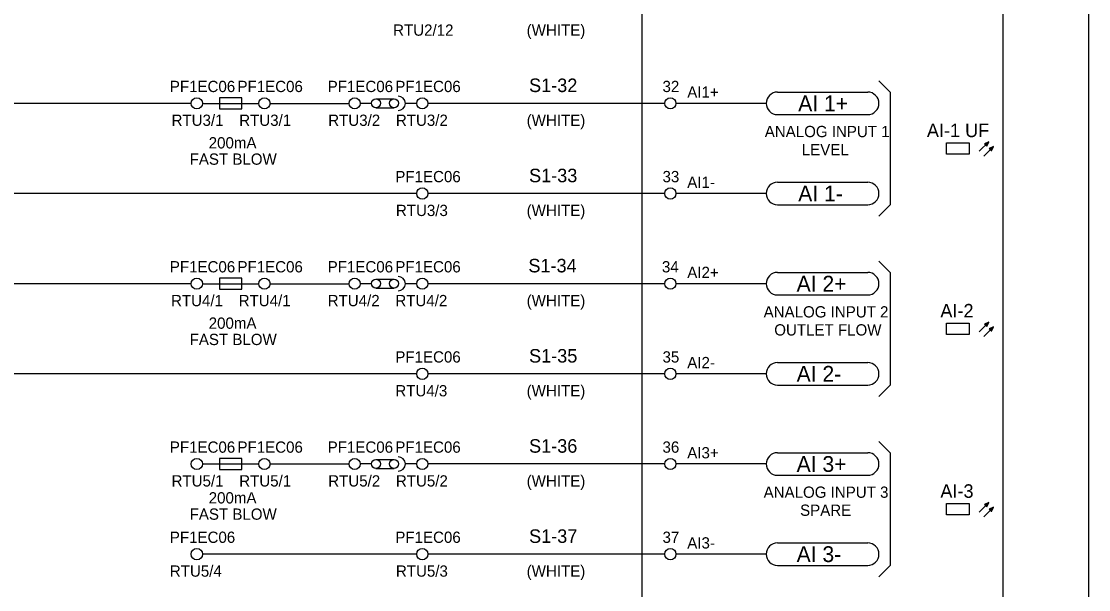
# Model space of a CAD drawing. Extents: x 0 to 841, y 0 to 594.
# Drawn here: x 592.3 to 829, y 132.1 to 258.2 of the extents above; entities that cross this region are included whole.
import ezdxf

# ---------------------------------------------------------------- set-up
doc = ezdxf.new("R2010")
doc.units = 0
for name, color, linetype in [('A1BORDER', 7, 'Continuous'), ('Level 1', 7, 'Continuous'), ('Level 10', 7, 'Continuous')]:
    doc.layers.add(name, color=color, linetype=linetype)

msp = doc.modelspace()

# ---------------------------------------------------------------- linework, layer by layer
at = {"layer": 'A1BORDER'}
msp.add_line((829, 581), (829, 15), dxfattribs=at)
at = {"layer": 'Level 1'}
for p, q in [((760, 242.5), (780, 242.5)), ((630, 240), (480, 240)), ((632.5, 240), (645, 240)), ((647.5, 240), (665, 240)), ((670, 240), (667.5, 240)), ((670.98, 241.03), (674.98, 241.03)), ((670.98, 239.03), (674.98, 239.03)), ((680, 240), (677.5, 240)), ((735, 240), (682.5, 240)), ((757.5, 240), (737.5, 240)), ((760, 237.5), (780, 237.5)), ((760, 222.5), (780, 222.5)), ((680, 220), (480, 220)), ((735, 220), (682.5, 220)), ((757.5, 220), (737.5, 220)), ((760, 217.5), (780, 217.5)), ((760, 202.5), (780, 202.5)), ((630, 200), (480, 200)), ((632.5, 200), (645, 200)), ((647.5, 200), (665, 200)), ((670, 200), (667.5, 200)), ((670.98, 201.03), (674.98, 201.03)), ((670.98, 199.03), (674.98, 199.03)), ((680, 200), (677.5, 200)), ((735, 200), (682.5, 200)), ((757.5, 200), (737.5, 200)), ((760, 197.5), (780, 197.5)), ((760, 182.5), (780, 182.5)), ((680, 180), (480, 180)), ((735, 180), (682.5, 180)), ((757.5, 180), (737.5, 180)), ((760, 177.5), (780, 177.5)), ((670.98, 161.03), (674.98, 161.03)), ((760, 162.5), (780, 162.5)), ((632.5, 160), (645, 160)), ((647.5, 160), (665, 160)), ((670, 160), (667.5, 160)), ((670.98, 159.03), (674.98, 159.03)), ((680, 160), (677.5, 160)), ((735, 160), (682.5, 160)), ((757.5, 160), (737.5, 160)), ((760, 157.5), (780, 157.5)), ((760, 142.5), (780, 142.5)), ((680, 140), (632.5, 140)), ((735, 140), (682.5, 140)), ((757.5, 140), (737.5, 140)), ((760, 137.5), (780, 137.5))]:
    msp.add_line(p, q, dxfattribs=at)
for points in [[(810, 553.95), (810, 80), (730, 80), (730, 546.05)], [(782.5, 245), (785, 242.5), (785, 217.5), (782.5, 215)], [(782.5, 205), (785, 202.5), (785, 177.5), (782.5, 175)], [(782.5, 165), (785, 162.5), (785, 137.5), (782.5, 135)]]:
    msp.add_lwpolyline(points, dxfattribs=at)
for points in [[(636.25, 238.75), (641.25, 238.75), (641.25, 241.25), (636.25, 241.25)], [(797.5, 231.25), (802.5, 231.25), (802.5, 228.75), (797.5, 228.75)], [(636.25, 198.75), (641.25, 198.75), (641.25, 201.25), (636.25, 201.25)], [(797.5, 191.25), (802.5, 191.25), (802.5, 188.75), (797.5, 188.75)], [(636.25, 158.75), (641.25, 158.75), (641.25, 161.25), (636.25, 161.25)], [(797.5, 151.25), (802.5, 151.25), (802.5, 148.75), (797.5, 148.75)]]:
    msp.add_lwpolyline(points, close=True, dxfattribs=at)
for centre in [(670.98, 240.03), (674.98, 240.03), (670.98, 200.03), (674.98, 200.03), (670.98, 160.03), (674.98, 160.03)]:
    msp.add_circle(centre, 1, dxfattribs=at)
for centre, start, end in [((760, 240), 90, 270), ((780, 240), 270, 90), ((760, 220), 90, 270), ((780, 220), 270, 90), ((760, 200), 90, 270), ((780, 200), 270, 90), ((760, 180), 90, 270), ((780, 180), 270, 90), ((760, 160), 90, 270), ((780, 160), 270, 90), ((760, 140), 90, 270), ((780, 140), 270, 90)]:
    msp.add_arc(centre, 2.5, start, end, dxfattribs=at)
at = {"layer": 'Level 10'}
for p, q in [((804.73, 229.36), (806.86, 231.48)), ((805.79, 228.3), (807.91, 230.42)), ((805.96, 231.08), (806.67, 231.08)), ((806, 230.93), (806.61, 230.93)), ((806.14, 230.78), (806.53, 230.78)), ((806.29, 231.22), (806.74, 231.22)), ((806.3, 230.62), (806.47, 230.62)), ((806.62, 231.38), (806.81, 231.38)), ((807.02, 230.02), (807.73, 230.02)), ((807.06, 229.87), (807.66, 229.87)), ((807.21, 229.72), (807.6, 229.72)), ((807.35, 230.16), (807.8, 230.16)), ((807.36, 229.56), (807.53, 229.56)), ((807.68, 230.31), (807.87, 230.31)), ((804.73, 189.35), (806.86, 191.48)), ((805.79, 188.3), (807.91, 190.42)), ((805.96, 191.08), (806.67, 191.08)), ((806, 190.93), (806.61, 190.93)), ((806.14, 190.78), (806.53, 190.78)), ((806.29, 191.22), (806.74, 191.22)), ((806.3, 190.62), (806.47, 190.62)), ((806.62, 191.38), (806.81, 191.38)), ((807.02, 190.02), (807.73, 190.02)), ((807.06, 189.87), (807.66, 189.87)), ((807.21, 189.72), (807.6, 189.72)), ((807.35, 190.16), (807.8, 190.16)), ((807.36, 189.56), (807.53, 189.56)), ((807.68, 190.31), (807.87, 190.31)), ((804.73, 149.35), (806.86, 151.48)), ((805.79, 148.3), (807.91, 150.42)), ((805.96, 151.08), (806.67, 151.08)), ((806, 150.93), (806.61, 150.93)), ((806.14, 150.78), (806.53, 150.78)), ((806.29, 151.22), (806.74, 151.22)), ((806.3, 150.62), (806.47, 150.62)), ((806.62, 151.38), (806.81, 151.38)), ((807.02, 150.02), (807.73, 150.02)), ((807.06, 149.87), (807.66, 149.87)), ((807.21, 149.72), (807.6, 149.72)), ((807.35, 150.16), (807.8, 150.16)), ((807.36, 149.56), (807.53, 149.56)), ((807.68, 150.31), (807.87, 150.31))]:
    msp.add_line(p, q, dxfattribs=at)
for points in [[(806.86, 231.48), (805.88, 231.04), (806.41, 230.5)], [(807.91, 230.42), (806.94, 229.98), (807.48, 229.44)], [(806.86, 191.48), (805.88, 191.04), (806.41, 190.5)], [(807.91, 190.42), (806.94, 189.98), (807.48, 189.44)], [(806.86, 151.48), (805.88, 151.04), (806.41, 150.5)], [(807.91, 150.42), (806.94, 149.98), (807.48, 149.44)]]:
    msp.add_lwpolyline(points, close=True, dxfattribs=at)
for centre in [(631.25, 240), (646.25, 240), (666.25, 240), (681.25, 240), (736.25, 240), (681.25, 220), (736.25, 220), (631.25, 200), (646.25, 200), (666.25, 200), (681.25, 200), (736.25, 200), (681.25, 180), (736.25, 180), (631.25, 160), (646.25, 160), (666.25, 160), (681.25, 160), (736.25, 160), (631.25, 140), (681.25, 140), (736.25, 140)]:
    msp.add_circle(centre, 1.25, dxfattribs=at)
for centre in [(675.9, 240), (675.9, 200), (675.9, 160)]:
    msp.add_arc(centre, 1.6, 270, 90, dxfattribs=at)

# ---------------------------------------------------------------- texts
at = {"layer": 'Level 1'}
for s, height, p in [('RTU2/12', 2.5, (674.78, 255)), ('(WHITE)', 2.5, (704.39, 255)), ('PF1EC06', 2.5, (625.27, 242.5)), ('PF1EC06', 2.5, (640.27, 242.5)), ('PF1EC06', 2.5, (660.27, 242.5)), ('PF1EC06', 2.5, (675.27, 242.5)), ('S1-32', 3, (704.92, 242.5)), ('32', 2.5, (734.51, 242.5)), ('AI1+', 2.5, (740, 241.25)), ('AI 1+', 3.5, (764.6, 238.25)), ('RTU3/1', 2.5, (625.65, 235)), ('RTU3/1', 2.5, (640.65, 235)), ('RTU3/2', 2.5, (660.39, 235)), ('RTU3/2', 2.5, (675.39, 235)), ('(WHITE)', 2.5, (704.39, 235)), ('ANALOG INPUT 1', 2.5, (757.18, 232.5)), ('AI-1 UF', 3, (793.13, 232.5)), ('200mA', 2.5, (633.89, 230)), ('LEVEL', 2.5, (765.39, 228.5)), ('FAST BLOW', 2.5, (629.66, 226.38)), ('PF1EC06', 2.5, (675.27, 222.5)), ('S1-33', 3, (704.92, 222.5)), ('33', 2.5, (734.51, 222.5)), ('AI1-', 2.5, (740, 221.25)), ('AI 1-', 3.5, (764.6, 218.25)), ('RTU3/3', 2.5, (675.4, 215)), ('(WHITE)', 2.5, (704.39, 215)), ('PF1EC06', 2.5, (625.27, 202.5)), ('PF1EC06', 2.5, (640.27, 202.5)), ('PF1EC06', 2.5, (660.27, 202.5)), ('PF1EC06', 2.5, (675.27, 202.5)), ('S1-34', 3, (704.77, 202.5)), ('34', 2.5, (734.38, 202.5)), ('AI2+', 2.5, (740, 201.25)), ('AI 2+', 3.5, (764.25, 198.25)), ('RTU4/1', 2.5, (625.53, 195)), ('RTU4/1', 2.5, (640.53, 195)), ('RTU4/2', 2.5, (660.27, 195)), ('RTU4/2', 2.5, (675.27, 195)), ('(WHITE)', 2.5, (704.39, 195)), ('ANALOG INPUT 2', 2.5, (756.93, 192.5)), ('AI-2', 3, (796.12, 192.5)), ('200mA', 2.5, (633.89, 190)), ('OUTLET FLOW', 2.5, (759.29, 188.5)), ('FAST BLOW', 2.5, (629.66, 186.38)), ('PF1EC06', 2.5, (675.27, 182.5)), ('S1-35', 3, (704.92, 182.5)), ('35', 2.5, (734.51, 182.5)), ('AI2-', 2.5, (740, 181.25)), ('AI 2-', 3.5, (764.25, 178.25)), ('RTU4/3', 2.5, (675.27, 175)), ('(WHITE)', 2.5, (704.39, 175)), ('PF1EC06', 2.5, (625.27, 162.5)), ('PF1EC06', 2.5, (640.27, 162.5)), ('PF1EC06', 2.5, (660.27, 162.5)), ('PF1EC06', 2.5, (675.27, 162.5)), ('S1-36', 3, (704.92, 162.5)), ('36', 2.5, (734.51, 162.5)), ('AI3+', 2.5, (740, 161.25)), ('AI 3+', 3.5, (764.25, 158.25)), ('RTU5/1', 2.5, (625.65, 155)), ('RTU5/1', 2.5, (640.65, 155)), ('RTU5/2', 2.5, (660.39, 155)), ('RTU5/2', 2.5, (675.39, 155)), ('(WHITE)', 2.5, (704.39, 155)), ('ANALOG INPUT 3', 2.5, (756.93, 152.5)), ('AI-3', 3, (796.12, 152.5)), ('200mA', 2.5, (633.89, 151.25)), ('FAST BLOW', 2.5, (629.66, 147.63)), ('SPARE', 2.5, (765.02, 148.5)), ('PF1EC06', 2.5, (625.27, 142.5)), ('PF1EC06', 2.5, (675.27, 142.5)), ('S1-37', 3, (704.92, 142.5)), ('37', 2.5, (734.51, 142.5)), ('AI3-', 2.5, (740, 141.25)), ('AI 3-', 3.5, (764.25, 138.25)), ('RTU5/4', 2.5, (625.27, 135)), ('RTU5/3', 2.5, (675.4, 135)), ('(WHITE)', 2.5, (704.39, 135))]:
    msp.add_text(s, height=height, dxfattribs=at).set_placement(p)

doc.saveas('drawing.dxf')
